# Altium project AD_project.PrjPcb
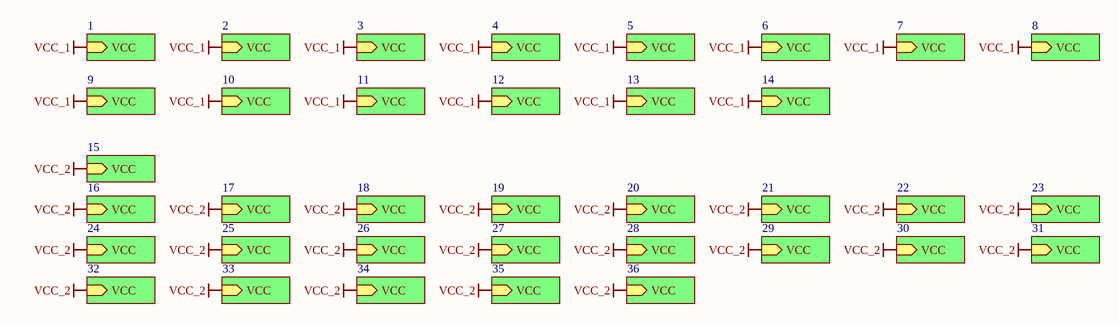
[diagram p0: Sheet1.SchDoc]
2 sheets, 324 parts. Net scope: hierarchical (ports join the sheet entries above them; power ports are global).
Board file: PCB2.PcbDoc
Sheets:
  Sheet1.SchDoc
    1 = PCB.SchDoc
    9 = PCB.SchDoc
    16 = PCB.SchDoc
    24 = PCB.SchDoc
    32 = PCB.SchDoc
    2 = PCB.SchDoc
    10 = PCB.SchDoc
    17 = PCB.SchDoc
    25 = PCB.SchDoc
    33 = PCB.SchDoc
    3 = PCB.SchDoc
    11 = PCB.SchDoc
    18 = PCB.SchDoc
    26 = PCB.SchDoc
    34 = PCB.SchDoc
    4 = PCB.SchDoc
    12 = PCB.SchDoc
    19 = PCB.SchDoc
    27 = PCB.SchDoc
    35 = PCB.SchDoc
    5 = PCB.SchDoc
    13 = PCB.SchDoc
    20 = PCB.SchDoc
    28 = PCB.SchDoc
    36 = PCB.SchDoc
    6 = PCB.SchDoc
    14 = PCB.SchDoc
    21 = PCB.SchDoc
    29 = PCB.SchDoc
    7 = PCB.SchDoc
    15 = PCB.SchDoc
    22 = PCB.SchDoc
    30 = PCB.SchDoc
    8 = PCB.SchDoc
    23 = PCB.SchDoc
    31 = PCB.SchDoc

## Sheet Sheet1.SchDoc
size A

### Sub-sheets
1 = PCB.SchDoc: VCC
2 = PCB.SchDoc: VCC
3 = PCB.SchDoc: VCC
4 = PCB.SchDoc: VCC
5 = PCB.SchDoc: VCC
6 = PCB.SchDoc: VCC
7 = PCB.SchDoc: VCC
8 = PCB.SchDoc: VCC
9 = PCB.SchDoc: VCC
10 = PCB.SchDoc: VCC
11 = PCB.SchDoc: VCC
12 = PCB.SchDoc: VCC
13 = PCB.SchDoc: VCC
14 = PCB.SchDoc: VCC
15 = PCB.SchDoc: VCC
16 = PCB.SchDoc: VCC
17 = PCB.SchDoc: VCC
18 = PCB.SchDoc: VCC
19 = PCB.SchDoc: VCC
20 = PCB.SchDoc: VCC
21 = PCB.SchDoc: VCC
22 = PCB.SchDoc: VCC
23 = PCB.SchDoc: VCC
24 = PCB.SchDoc: VCC
25 = PCB.SchDoc: VCC
26 = PCB.SchDoc: VCC
27 = PCB.SchDoc: VCC
28 = PCB.SchDoc: VCC
29 = PCB.SchDoc: VCC
30 = PCB.SchDoc: VCC
31 = PCB.SchDoc: VCC
32 = PCB.SchDoc: VCC
33 = PCB.SchDoc: VCC
34 = PCB.SchDoc: VCC
35 = PCB.SchDoc: VCC
36 = PCB.SchDoc: VCC

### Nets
VCC_1: sheet 1/VCC, sheet 9/VCC, sheet 2/VCC, sheet 10/VCC, sheet 3/VCC, sheet 11/VCC, sheet 4/VCC, sheet 12/VCC, sheet 5/VCC, sheet 13/VCC, sheet 6/VCC, sheet 14/VCC, sheet 7/VCC, sheet 8/VCC
VCC_2: sheet 16/VCC, sheet 24/VCC, sheet 32/VCC, sheet 17/VCC, sheet 25/VCC, sheet 33/VCC, sheet 18/VCC, sheet 26/VCC, sheet 34/VCC, sheet 19/VCC, sheet 27/VCC, sheet 35/VCC, sheet 20/VCC, sheet 28/VCC, sheet 36/VCC, sheet 21/VCC, sheet 29/VCC, sheet 15/VCC, sheet 22/VCC, sheet 30/VCC, sheet 23/VCC, sheet 31/VCC

## Sheet PCB.SchDoc
size A2
Used 36 times, as channels 1, 9, 16, 24, 32, 2, 10, 17, 25, 33, 3, 11, 18, 26, 34, 4, 12, 19, 27, 35, 5, 13, 20, 28, 36, 6, 14, 21, 29, 7, 15, 22, 30, 8, 23, 31. Parts and nets are listed once, with the designators drawn on the sheet.
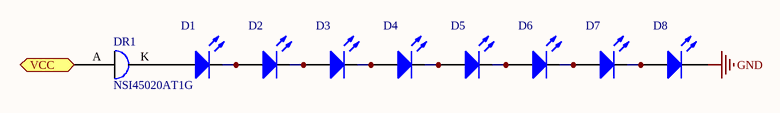
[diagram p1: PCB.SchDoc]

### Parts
D1  LED0  [LED-0]  (value not drawn)
D2  LED0  [LED-0]  (value not drawn)
D3  LED0  [LED-0]  (value not drawn)
D4  LED0  [LED-0]  (value not drawn)
D5  LED0  [LED-0]  (value not drawn)
D6  LED0  [LED-0]  (value not drawn)
D7  LED0  [LED-0]  (value not drawn)
D8  LED0  [LED-0]  (value not drawn)
DR1  NSI45020AT1G  [NSI45020AT1G]

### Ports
VCC

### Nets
GND: D8.2(K)
VCC: DR1.A ; port VCC
NetD1_1: D1.1(A) DR1.K
NetD1_2: D1.2(K) D2.1(A)
NetD2_2: D2.2(K) D3.1(A)
NetD3_2: D3.2(K) D4.1(A)
NetD4_2: D4.2(K) D5.1(A)
NetD5_2: D5.2(K) D6.1(A)
NetD6_2: D6.2(K) D7.1(A)
NetD7_2: D7.2(K) D8.1(A)

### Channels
1: designators end in _1; ports VCC=VCC_1
9: designators end in _9; ports VCC=VCC_1
16: designators end in _16; ports VCC=VCC_2
24: designators end in _24; ports VCC=VCC_2
32: designators end in _32; ports VCC=VCC_2
2: designators end in _2; ports VCC=VCC_1
10: designators end in _10; ports VCC=VCC_1
17: designators end in _17; ports VCC=VCC_2
25: designators end in _25; ports VCC=VCC_2
33: designators end in _33; ports VCC=VCC_2
3: designators end in _3; ports VCC=VCC_1
11: designators end in _11; ports VCC=VCC_1
18: designators end in _18; ports VCC=VCC_2
26: designators end in _26; ports VCC=VCC_2
34: designators end in _34; ports VCC=VCC_2
4: designators end in _4; ports VCC=VCC_1
12: designators end in _12; ports VCC=VCC_1
19: designators end in _19; ports VCC=VCC_2
27: designators end in _27; ports VCC=VCC_2
35: designators end in _35; ports VCC=VCC_2
5: designators end in _5; ports VCC=VCC_1
13: designators end in _13; ports VCC=VCC_1
20: designators end in _20; ports VCC=VCC_2
28: designators end in _28; ports VCC=VCC_2
36: designators end in _36; ports VCC=VCC_2
6: designators end in _6; ports VCC=VCC_1
14: designators end in _14; ports VCC=VCC_1
21: designators end in _21; ports VCC=VCC_2
29: designators end in _29; ports VCC=VCC_2
7: designators end in _7; ports VCC=VCC_1
15: designators end in _15; ports VCC=VCC_2
22: designators end in _22; ports VCC=VCC_2
30: designators end in _30; ports VCC=VCC_2
8: designators end in _8; ports VCC=VCC_1
23: designators end in _23; ports VCC=VCC_2
31: designators end in _31; ports VCC=VCC_2

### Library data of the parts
D1-D8 = LED0: Typical INFRARED GaAs LED

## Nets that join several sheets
GND: 1 (D8_1.2), 9 (D8_9.2), 16 (D8_16.2), 24 (D8_24.2), 32 (D8_32.2), 2 (D8_2.2), 10 (D8_10.2), 17 (D8_17.2), 25 (D8_25.2), 33 (D8_33.2), 3 (D8_3.2), 11 (D8_11.2), 18 (D8_18.2), 26 (D8_26.2), 34 (D8_34.2), 4 (D8_4.2), 12 (D8_12.2), 19 (D8_19.2), 27 (D8_27.2), 35 (D8_35.2), 5 (D8_5.2), 13 (D8_13.2), 20 (D8_20.2), 28 (D8_28.2), 36 (D8_36.2), 6 (D8_6.2), 14 (D8_14.2), 21 (D8_21.2), 29 (D8_29.2), 7 (D8_7.2), 15 (D8_15.2), 22 (D8_22.2), 30 (D8_30.2), 8 (D8_8.2), 23 (D8_23.2), 31 (D8_31.2)
VCC_1: 1 (DR1_1.A), 9 (DR1_9.A), 2 (DR1_2.A), 10 (DR1_10.A), 3 (DR1_3.A), 11 (DR1_11.A), 4 (DR1_4.A), 12 (DR1_12.A), 5 (DR1_5.A), 13 (DR1_13.A), 6 (DR1_6.A), 14 (DR1_14.A), 7 (DR1_7.A), 8 (DR1_8.A)
VCC_2: 16 (DR1_16.A), 24 (DR1_24.A), 32 (DR1_32.A), 17 (DR1_17.A), 25 (DR1_25.A), 33 (DR1_33.A), 18 (DR1_18.A), 26 (DR1_26.A), 34 (DR1_34.A), 19 (DR1_19.A), 27 (DR1_27.A), 35 (DR1_35.A), 20 (DR1_20.A), 28 (DR1_28.A), 36 (DR1_36.A), 21 (DR1_21.A), 29 (DR1_29.A), 15 (DR1_15.A), 22 (DR1_22.A), 30 (DR1_30.A), 23 (DR1_23.A), 31 (DR1_31.A)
